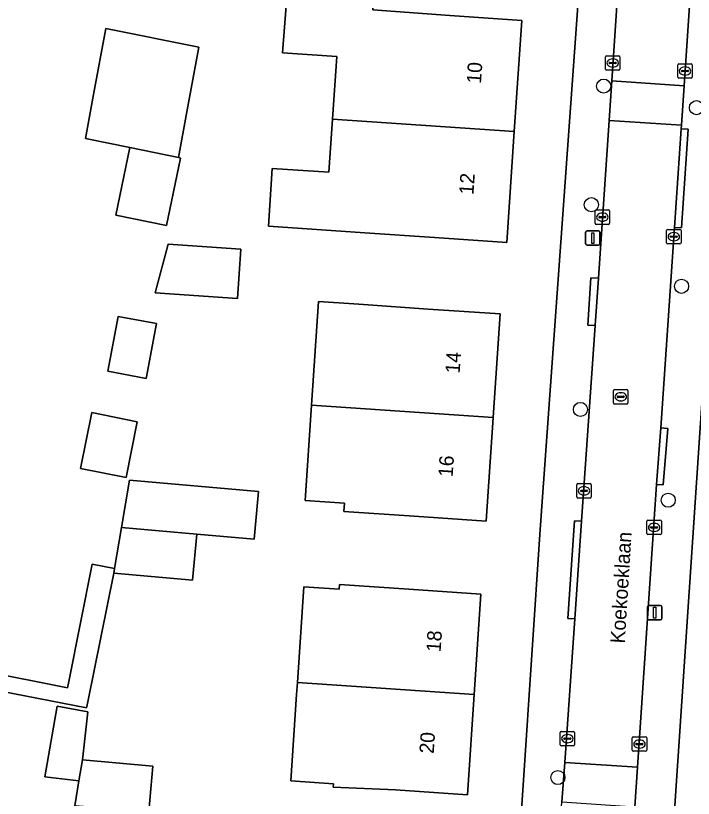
# Model space of a CAD drawing. Extents: x 161772 to 163126, y 383092 to 383917.
# Drawn here: x 162280.9 to 162327.9, y 383695.1 to 383749.3 of the extents above; entities that cross this region are included whole.
import ezdxf

# ---------------------------------------------------------------- set-up
doc = ezdxf.new("R2010")
doc.units = 0
for name, color, linetype in [('IMGEO_Boom', 7, 'Continuous'), ('IMGEO_Erf', 7, 'Continuous'), ('IMGEO_Kolk', 7, 'Continuous'), ('IMGEO_Lichtmast', 7, 'Continuous'), ('IMGEO_Openbare_ruimte_label', 7, 'Continuous'), ('IMGEO_Pand', 7, 'Continuous'), ('IMGEO_Pand_nummerreeks', 7, 'Continuous'), ('IMGEO_Rijbaan_lokaal_open', 7, 'Continuous'), ('IMGEO_Rioolput', 7, 'Continuous'), ('IMGEO_Voetpad_open', 7, 'Continuous')]:
    doc.layers.add(name, color=color, linetype=linetype)

msp = doc.modelspace()

# ---------------------------------------------------------------- linework, layer by layer
at = {"layer": 'IMGEO_Boom'}
for centre in [(162321.644, 383744.434), (162328.073, 383742.944), (162320.793, 383736.224), (162327.037, 383730.571), (162320.033, 383722.041), (162326.116, 383715.758), (162318.474, 383696.551)]:
    msp.add_circle(centre, 0.489, dxfattribs=at)
at = {"layer": 'IMGEO_Erf'}
for points in [[(162299.403, 383746.742), (162299.661, 383750), (162299.672, 383750.137), (162300.148, 383750.103), (162300.308, 383752.363), (162305.822, 383751.973), (162305.662, 383749.713), (162310.984, 383749.336), (162315.971, 383748.985), (162315.45, 383741.3), (162314.929, 383733.617), (162309.941, 383733.955), (162305.103, 383734.283), (162298.425, 383734.735), (162298.696, 383738.734), (162302.623, 383738.468), (162302.872, 383742.151), (162303.166, 383746.487)], [(162285.756, 383740.815), (162286.321, 383743.851), (162287.171, 383748.42), (162293.617, 383747.135), (162292.783, 383742.649), (162292.195, 383739.486), (162292.33, 383739.458), (162291.363, 383734.774), (162287.868, 383735.496), (162288.836, 383740.18)], [(162290.575, 383730.125), (162291.495, 383733.496), (162296.514, 383733.156), (162296.283, 383729.739)], [(162301.905, 383729.514), (162304.69, 383729.325), (162309.487, 383729), (162314.475, 383728.662), (162313.989, 383721.488), (162313.503, 383714.317), (162308.515, 383714.655), (162303.661, 383714.984), (162303.699, 383715.545), (162300.971, 383715.729), (162301.419, 383722.343)], [(162287.302, 383724.693), (162288.016, 383728.491), (162290.685, 383727.989), (162289.971, 383724.192)], [(162286.195, 383721.823), (162289.349, 383721.19), (162288.575, 383717.33), (162285.421, 383717.963)], [(162300.384, 383702.301), (162300.44, 383703.136), (162300.889, 383709.766), (162303.331, 383709.601), (162303.352, 383709.916), (162308.161, 383709.591), (162313.149, 383709.253), (162312.679, 383702.308), (162312.208, 383695.359), (162307.22, 383695.697), (162302.923, 383695.892), (162302.938, 383696.111), (162299.978, 383696.311)], [(162283.807, 383701.505), (162285.929, 383701.094), (162285.552, 383697.785), (162290.417, 383697.342), (162290.147, 383694.191), (162285.017, 383694.602), (162285.306, 383696.324), (162282.944, 383696.598)]]:
    msp.add_lwpolyline(points, close=True, dxfattribs=at)
for points in [[(162313.196, 383652.957), (162317.249, 383713.725), (162319.862, 383750)], [(162329.513, 383738.311), (162323.298, 383645.721), (162324.273, 383644.745), (162401.886, 383657.92)], [(162278.578, 383703.948), (162284.515, 383702.757), (162284.601, 383703.204), (162286.234, 383711.335), (162287.776, 383711.032), (162288.253, 383713.871), (162288.804, 383717.152), (162297.73, 383716.357), (162297.436, 383713.053), (162293.462, 383713.407), (162293.178, 383710.225), (162287.722, 383710.711), (162285.922, 383701.797), (162285.84, 383701.374), (162277.263, 383703.035)]]:
    msp.add_lwpolyline(points, dxfattribs=at)
at = {"layer": 'IMGEO_Kolk'}
for p, q in [((162321.77, 383745.614), (162321.77, 383746.466)), ((162321.845, 383746.54), (162322.697, 383746.54)), ((162322.029, 383746.034), (162322.029, 383746.046)), ((162322.072, 383746.083), (162322.47, 383746.083)), ((162322.258, 383746.32), (162322.283, 383746.32)), ((162322.513, 383746.046), (162322.513, 383746.034)), ((162322.771, 383746.466), (162322.771, 383745.614)), ((162322.697, 383745.54), (162321.845, 383745.54)), ((162322.467, 383745.997), (162322.069, 383745.997)), ((162322.281, 383745.76), (162322.256, 383745.76)), ((162326.779, 383745.056), (162326.779, 383745.908)), ((162326.854, 383745.982), (162327.706, 383745.982)), ((162327.038, 383745.476), (162327.038, 383745.488)), ((162327.081, 383745.525), (162327.479, 383745.525)), ((162327.267, 383745.762), (162327.292, 383745.762)), ((162327.522, 383745.488), (162327.522, 383745.476)), ((162327.78, 383745.908), (162327.78, 383745.056)), ((162327.706, 383744.982), (162326.854, 383744.982)), ((162327.476, 383745.439), (162327.078, 383745.439)), ((162327.29, 383745.202), (162327.265, 383745.202)), ((162321.054, 383734.938), (162321.054, 383735.79)), ((162321.129, 383735.864), (162321.981, 383735.864)), ((162322.055, 383735.79), (162322.055, 383734.938)), ((162321.313, 383735.358), (162321.313, 383735.37)), ((162321.751, 383735.321), (162321.353, 383735.321)), ((162321.356, 383735.407), (162321.754, 383735.407)), ((162321.542, 383735.644), (162321.567, 383735.644)), ((162321.797, 383735.37), (162321.797, 383735.358)), ((162321.981, 383734.864), (162321.129, 383734.864)), ((162321.565, 383735.084), (162321.54, 383735.084)), ((162326.002, 383733.582), (162326.002, 383734.434)), ((162326.077, 383734.508), (162326.929, 383734.508)), ((162326.49, 383734.288), (162326.515, 383734.288)), ((162327.003, 383734.434), (162327.003, 383733.582)), ((162326.261, 383734.002), (162326.261, 383734.014)), ((162326.699, 383733.965), (162326.301, 383733.965)), ((162326.304, 383734.051), (162326.702, 383734.051)), ((162326.513, 383733.728), (162326.488, 383733.728)), ((162326.745, 383734.014), (162326.745, 383734.002)), ((162326.929, 383733.508), (162326.077, 383733.508)), ((162319.782, 383715.981), (162319.782, 383716.833)), ((162319.857, 383716.907), (162320.709, 383716.907)), ((162320.783, 383716.833), (162320.783, 383715.981)), ((162320.041, 383716.401), (162320.041, 383716.413)), ((162320.479, 383716.364), (162320.081, 383716.364)), ((162320.084, 383716.45), (162320.482, 383716.45)), ((162320.27, 383716.687), (162320.295, 383716.687)), ((162320.525, 383716.413), (162320.525, 383716.401)), ((162320.709, 383715.907), (162319.857, 383715.907)), ((162320.293, 383716.127), (162320.268, 383716.127)), ((162324.639, 383713.448), (162324.639, 383714.3)), ((162324.714, 383714.374), (162325.566, 383714.374)), ((162325.127, 383714.154), (162325.152, 383714.154)), ((162325.64, 383714.3), (162325.64, 383713.448)), ((162324.898, 383713.868), (162324.898, 383713.88)), ((162325.336, 383713.831), (162324.938, 383713.831)), ((162324.941, 383713.917), (162325.339, 383713.917)), ((162325.15, 383713.594), (162325.125, 383713.594)), ((162325.382, 383713.88), (162325.382, 383713.868)), ((162325.566, 383713.374), (162324.714, 383713.374)), ((162318.631, 383698.819), (162318.631, 383699.671)), ((162318.706, 383699.745), (162319.558, 383699.745)), ((162319.119, 383699.525), (162319.144, 383699.525)), ((162319.632, 383699.671), (162319.632, 383698.819)), ((162318.89, 383699.239), (162318.89, 383699.251)), ((162319.328, 383699.202), (162318.93, 383699.202)), ((162318.933, 383699.288), (162319.331, 383699.288)), ((162319.142, 383698.965), (162319.117, 383698.965)), ((162319.374, 383699.251), (162319.374, 383699.239)), ((162323.623, 383698.442), (162323.623, 383699.294)), ((162323.698, 383699.368), (162324.55, 383699.368)), ((162323.882, 383698.862), (162323.882, 383698.874)), ((162323.925, 383698.911), (162324.323, 383698.911)), ((162324.111, 383699.148), (162324.136, 383699.148)), ((162324.366, 383698.874), (162324.366, 383698.862)), ((162324.624, 383699.294), (162324.624, 383698.442)), ((162319.558, 383698.745), (162318.706, 383698.745)), ((162324.55, 383698.368), (162323.698, 383698.368)), ((162324.32, 383698.825), (162323.922, 383698.825)), ((162324.134, 383698.588), (162324.109, 383698.588))]:
    msp.add_line(p, q, dxfattribs=at)
for points in [[(162321.77, 383745.614), (162321.77, 383746.466)], [(162321.845, 383746.54), (162322.697, 383746.54)], [(162322.771, 383746.466), (162322.771, 383745.614)], [(162322.697, 383745.54), (162321.845, 383745.54)], [(162326.779, 383745.056), (162326.779, 383745.908)], [(162326.854, 383745.982), (162327.706, 383745.982)], [(162327.78, 383745.908), (162327.78, 383745.056)], [(162327.706, 383744.982), (162326.854, 383744.982)], [(162321.054, 383734.938), (162321.054, 383735.79)], [(162321.129, 383735.864), (162321.981, 383735.864)], [(162322.055, 383735.79), (162322.055, 383734.938)], [(162321.981, 383734.864), (162321.129, 383734.864)], [(162326.002, 383733.582), (162326.002, 383734.434)], [(162326.077, 383734.508), (162326.929, 383734.508)], [(162327.003, 383734.434), (162327.003, 383733.582)], [(162326.929, 383733.508), (162326.077, 383733.508)], [(162319.782, 383715.981), (162319.782, 383716.833)], [(162319.857, 383716.907), (162320.709, 383716.907)], [(162320.783, 383716.833), (162320.783, 383715.981)], [(162320.709, 383715.907), (162319.857, 383715.907)], [(162324.639, 383713.448), (162324.639, 383714.3)], [(162324.714, 383714.374), (162325.566, 383714.374)], [(162325.64, 383714.3), (162325.64, 383713.448)], [(162325.566, 383713.374), (162324.714, 383713.374)], [(162318.631, 383698.819), (162318.631, 383699.671)], [(162318.706, 383699.745), (162319.558, 383699.745)], [(162319.632, 383699.671), (162319.632, 383698.819)], [(162323.623, 383698.442), (162323.623, 383699.294)], [(162323.698, 383699.368), (162324.55, 383699.368)], [(162324.624, 383699.294), (162324.624, 383698.442)], [(162319.558, 383698.745), (162318.706, 383698.745)], [(162324.55, 383698.368), (162323.698, 383698.368)]]:
    msp.add_lwpolyline(points, dxfattribs=at)
for centre, radius, start, end in [((162321.847, 383746.464), 0.0765, 91.552, 178.448), ((162321.847, 383746.464), 0.0765, 91.552, 178.448), ((162322.069, 383746.043), 0.0403, 85.8775, 175.7526), ((162322.066, 383746.033), 0.0366, 178.938, 274.7102), ((162322.47, 383746.04), 0.043, 264.8664, 352.4533), ((162322.474, 383746.045), 0.0386, 1.7309, 96.639), ((162322.695, 383746.464), 0.0765, 1.552, 88.448), ((162322.695, 383746.464), 0.0765, 1.552, 88.448), ((162321.847, 383745.616), 0.0765, 181.552, 268.448), ((162321.847, 383745.616), 0.0765, 181.552, 268.448), ((162322.695, 383745.616), 0.0765, 271.552, 358.448), ((162322.695, 383745.616), 0.0765, 271.552, 358.448), ((162326.856, 383745.906), 0.0765, 91.552, 178.448), ((162326.856, 383745.906), 0.0765, 91.552, 178.448), ((162327.078, 383745.485), 0.0403, 85.8775, 175.7526), ((162327.075, 383745.475), 0.0366, 178.938, 274.7102), ((162327.479, 383745.482), 0.043, 264.8664, 352.4533), ((162327.483, 383745.487), 0.0386, 1.7309, 96.639), ((162327.704, 383745.906), 0.0765, 1.552, 88.448), ((162327.704, 383745.906), 0.0765, 1.552, 88.448), ((162326.856, 383745.058), 0.0765, 181.552, 268.448), ((162326.856, 383745.058), 0.0765, 181.552, 268.448), ((162327.704, 383745.058), 0.0765, 271.552, 358.448), ((162327.704, 383745.058), 0.0765, 271.552, 358.448), ((162321.131, 383735.788), 0.0765, 91.552, 178.448), ((162321.131, 383735.788), 0.0765, 91.552, 178.448), ((162321.979, 383735.788), 0.0765, 1.552, 88.448), ((162321.979, 383735.788), 0.0765, 1.552, 88.448), ((162321.353, 383735.367), 0.0403, 85.8775, 175.7526), ((162321.35, 383735.357), 0.0366, 178.938, 274.7102), ((162321.754, 383735.364), 0.043, 264.8664, 352.4533), ((162321.758, 383735.369), 0.0386, 1.7309, 96.639), ((162321.131, 383734.94), 0.0765, 181.552, 268.448), ((162321.131, 383734.94), 0.0765, 181.552, 268.448), ((162321.979, 383734.94), 0.0765, 271.552, 358.448), ((162321.979, 383734.94), 0.0765, 271.552, 358.448), ((162326.079, 383734.432), 0.0765, 91.552, 178.448), ((162326.079, 383734.432), 0.0765, 91.552, 178.448), ((162326.927, 383734.432), 0.0765, 1.552, 88.448), ((162326.927, 383734.432), 0.0765, 1.552, 88.448), ((162326.079, 383733.584), 0.0765, 181.552, 268.448), ((162326.079, 383733.584), 0.0765, 181.552, 268.448), ((162326.301, 383734.011), 0.0403, 85.8775, 175.7526), ((162326.298, 383734.001), 0.0366, 178.938, 274.7102), ((162326.702, 383734.008), 0.043, 264.8664, 352.4533), ((162326.706, 383734.013), 0.0386, 1.7309, 96.639), ((162326.927, 383733.584), 0.0765, 271.552, 358.448), ((162326.927, 383733.584), 0.0765, 271.552, 358.448), ((162319.859, 383716.831), 0.0765, 91.552, 178.448), ((162319.859, 383716.831), 0.0765, 91.552, 178.448), ((162320.707, 383716.831), 0.0765, 1.552, 88.448), ((162320.707, 383716.831), 0.0765, 1.552, 88.448), ((162320.081, 383716.41), 0.0403, 85.8775, 175.7526), ((162320.078, 383716.4), 0.0366, 178.938, 274.7102), ((162320.482, 383716.407), 0.043, 264.8664, 352.4533), ((162320.486, 383716.412), 0.0386, 1.7309, 96.639), ((162319.859, 383715.983), 0.0765, 181.552, 268.448), ((162319.859, 383715.983), 0.0765, 181.552, 268.448), ((162320.707, 383715.983), 0.0765, 271.552, 358.448), ((162320.707, 383715.983), 0.0765, 271.552, 358.448), ((162324.716, 383714.298), 0.0765, 91.552, 178.448), ((162324.716, 383714.298), 0.0765, 91.552, 178.448), ((162325.564, 383714.298), 0.0765, 1.552, 88.448), ((162325.564, 383714.298), 0.0765, 1.552, 88.448), ((162324.938, 383713.877), 0.0403, 85.8775, 175.7526), ((162324.935, 383713.867), 0.0366, 178.938, 274.7102), ((162325.339, 383713.874), 0.043, 264.8664, 352.4533), ((162325.343, 383713.879), 0.0386, 1.7309, 96.639), ((162324.716, 383713.45), 0.0765, 181.552, 268.448), ((162324.716, 383713.45), 0.0765, 181.552, 268.448), ((162325.564, 383713.45), 0.0765, 271.552, 358.448), ((162325.564, 383713.45), 0.0765, 271.552, 358.448), ((162318.708, 383699.669), 0.0765, 91.552, 178.448), ((162318.708, 383699.669), 0.0765, 91.552, 178.448), ((162319.556, 383699.669), 0.0765, 1.552, 88.448), ((162319.556, 383699.669), 0.0765, 1.552, 88.448), ((162318.93, 383699.248), 0.0403, 85.8775, 175.7526), ((162318.927, 383699.238), 0.0366, 178.938, 274.7102), ((162319.331, 383699.245), 0.043, 264.8664, 352.4533), ((162319.335, 383699.25), 0.0386, 1.7309, 96.639), ((162323.7, 383699.292), 0.0765, 91.552, 178.448), ((162323.7, 383699.292), 0.0765, 91.552, 178.448), ((162323.922, 383698.871), 0.0403, 85.8775, 175.7526), ((162323.919, 383698.861), 0.0366, 178.938, 274.7102), ((162324.323, 383698.868), 0.043, 264.8664, 352.4533), ((162324.327, 383698.873), 0.0386, 1.7309, 96.639), ((162324.548, 383699.292), 0.0765, 1.552, 88.448), ((162324.548, 383699.292), 0.0765, 1.552, 88.448), ((162318.708, 383698.821), 0.0765, 181.552, 268.448), ((162318.708, 383698.821), 0.0765, 181.552, 268.448), ((162319.556, 383698.821), 0.0765, 271.552, 358.448), ((162319.556, 383698.821), 0.0765, 271.552, 358.448), ((162323.7, 383698.444), 0.0765, 181.552, 268.448), ((162323.7, 383698.444), 0.0765, 181.552, 268.448), ((162324.548, 383698.444), 0.0765, 271.552, 358.448), ((162324.548, 383698.444), 0.0765, 271.552, 358.448)]:
    msp.add_arc(centre, radius, start, end, dxfattribs=at)
for centre, major_axis, ratio, start_param, end_param in [((162322.257, 383746.04), (-0.387, 0.002), 0.722429, 4.712389, 7.853982), ((162322.282, 383746.04), (-0.39, 0.002), 0.717154, 1.570796, 4.712389), ((162327.266, 383745.482), (-0.387, 0.002), 0.722429, 4.712389, 7.853982), ((162327.291, 383745.482), (-0.39, 0.002), 0.717154, 1.570796, 4.712389), ((162321.541, 383735.364), (-0.387, 0.002), 0.722429, 4.712389, 7.853982), ((162321.566, 383735.364), (-0.39, 0.002), 0.717154, 1.570796, 4.712389), ((162326.489, 383734.008), (-0.387, 0.002), 0.722429, 4.712389, 7.853982), ((162326.514, 383734.008), (-0.39, 0.002), 0.717154, 1.570796, 4.712389), ((162320.269, 383716.407), (-0.387, 0.002), 0.722429, 4.712389, 7.853982), ((162320.294, 383716.407), (-0.39, 0.002), 0.717154, 1.570796, 4.712389), ((162325.126, 383713.874), (-0.387, 0.002), 0.722429, 4.712389, 7.853982), ((162325.151, 383713.874), (-0.39, 0.002), 0.717154, 1.570796, 4.712389), ((162319.118, 383699.245), (-0.387, 0.002), 0.722429, 4.712389, 7.853982), ((162319.143, 383699.245), (-0.39, 0.002), 0.717154, 1.570796, 4.712389), ((162324.11, 383698.868), (-0.387, 0.002), 0.722429, 4.712389, 7.853982), ((162324.135, 383698.868), (-0.39, 0.002), 0.717154, 1.570796, 4.712389)]:
    msp.add_ellipse(centre, major_axis=major_axis, ratio=ratio, start_param=start_param, end_param=end_param, dxfattribs=at)
at = {"layer": 'IMGEO_Lichtmast'}
for p, q in [((162320.397, 383733.512), (162320.397, 383734.312)), ((162320.397, 383734.312), (162320.397, 383733.512)), ((162320.497, 383734.412), (162321.287, 383734.412)), ((162321.287, 383734.412), (162320.497, 383734.412)), ((162321.387, 383734.312), (162321.387, 383733.512)), ((162321.387, 383733.512), (162321.387, 383734.312)), ((162321.287, 383733.412), (162320.497, 383733.412)), ((162320.497, 383733.412), (162321.287, 383733.412)), ((162324.679, 383707.567), (162324.679, 383708.367)), ((162324.679, 383708.367), (162324.679, 383707.567)), ((162324.779, 383708.467), (162325.569, 383708.467)), ((162325.569, 383708.467), (162324.779, 383708.467)), ((162325.669, 383708.367), (162325.669, 383707.567)), ((162325.669, 383707.567), (162325.669, 383708.367)), ((162325.569, 383707.467), (162324.779, 383707.467)), ((162324.779, 383707.467), (162325.569, 383707.467))]:
    msp.add_line(p, q, dxfattribs=at)
for points in [[(162320.817, 383734.287), (162320.967, 383734.287), (162320.967, 383733.537), (162320.817, 383733.537), (162320.817, 383734.287)], [(162325.099, 383708.342), (162325.249, 383708.342), (162325.249, 383707.592), (162325.099, 383707.592), (162325.099, 383708.342)]]:
    msp.add_lwpolyline(points, dxfattribs=at)
for centre, start, end in [((162320.497, 383734.312), 90, 180), ((162320.497, 383734.312), 90, 180), ((162321.287, 383734.312), 0, 90), ((162321.287, 383734.312), 360, 90), ((162320.497, 383733.512), 180, 270), ((162320.497, 383733.512), 180, 270), ((162321.287, 383733.512), 270, 0), ((162321.287, 383733.512), 270, 0), ((162324.779, 383708.367), 90, 180), ((162324.779, 383708.367), 90, 180), ((162325.569, 383708.367), 0, 90), ((162325.569, 383708.367), 360, 90), ((162324.779, 383707.567), 180, 270), ((162324.779, 383707.567), 180, 270), ((162325.569, 383707.567), 270, 0), ((162325.569, 383707.567), 270, 0)]:
    msp.add_arc(centre, 0.1, start, end, dxfattribs=at)
at = {"layer": 'IMGEO_Pand'}
for points in [[(162315.971, 383748.985), (162310.984, 383749.336), (162305.662, 383749.713), (162305.822, 383751.973), (162300.308, 383752.363), (162300.148, 383750.103), (162299.672, 383750.137), (162299.661, 383750), (162299.403, 383746.742), (162303.166, 383746.487), (162302.872, 383742.151), (162315.45, 383741.3)], [(162288.836, 383740.18), (162292.195, 383739.486), (162292.783, 383742.649), (162293.617, 383747.135), (162287.171, 383748.42), (162286.321, 383743.851), (162285.756, 383740.815)], [(162315.45, 383741.3), (162302.872, 383742.151), (162302.623, 383738.468), (162298.696, 383738.734), (162298.425, 383734.735), (162305.103, 383734.283), (162309.941, 383733.955), (162314.929, 383733.617)], [(162288.836, 383740.18), (162287.868, 383735.496), (162291.363, 383734.774), (162292.33, 383739.458), (162292.195, 383739.486)], [(162291.495, 383733.496), (162290.575, 383730.125), (162296.283, 383729.739), (162296.514, 383733.156)], [(162301.419, 383722.343), (162313.989, 383721.488), (162314.475, 383728.662), (162309.487, 383729), (162304.69, 383729.325), (162301.905, 383729.514)], [(162289.971, 383724.192), (162290.685, 383727.989), (162288.016, 383728.491), (162287.302, 383724.693)], [(162301.419, 383722.343), (162300.971, 383715.729), (162303.699, 383715.545), (162303.661, 383714.984), (162308.515, 383714.655), (162313.503, 383714.317), (162313.989, 383721.488)], [(162288.575, 383717.33), (162289.349, 383721.19), (162286.195, 383721.823), (162285.421, 383717.963)], [(162297.73, 383716.357), (162288.804, 383717.152), (162288.253, 383713.871), (162293.462, 383713.407), (162297.436, 383713.053)], [(162293.462, 383713.407), (162288.253, 383713.871), (162287.776, 383711.032), (162287.722, 383710.711), (162293.178, 383710.225)], [(162300.44, 383703.136), (162312.679, 383702.308), (162313.149, 383709.253), (162308.161, 383709.591), (162303.352, 383709.916), (162303.331, 383709.601), (162300.889, 383709.766)], [(162300.44, 383703.136), (162300.384, 383702.301), (162299.978, 383696.311), (162302.938, 383696.111), (162302.923, 383695.892), (162307.22, 383695.697), (162312.208, 383695.359), (162312.679, 383702.308)], [(162283.807, 383701.505), (162282.944, 383696.598), (162285.306, 383696.324), (162285.552, 383697.785), (162285.929, 383701.094)], [(162285.552, 383697.785), (162285.306, 383696.324), (162285.017, 383694.602), (162290.147, 383694.191), (162290.417, 383697.342)]]:
    msp.add_lwpolyline(points, close=True, dxfattribs=at)
at = {"layer": 'IMGEO_Rijbaan_lokaal_open'}
for points in [[(162327.904, 383754.6), (162328.166, 383758.408), (162330.319, 383789.642), (162325.316, 383789.988), (162322.549, 383750), (162322.2, 383744.798), (162327.215, 383744.461), (162327.587, 383750)], [(162322.016, 383742.063), (162327.031, 383741.726), (162327.215, 383744.461), (162322.2, 383744.798)], [(162325.594, 383720.759), (162326.555, 383734.645), (162327.015, 383741.486), (162327.031, 383741.726), (162322.016, 383742.063), (162321.282, 383731.126), (162321.062, 383727.852), (162320.113, 383714.297), (162319.639, 383707.534), (162318.944, 383697.598), (162323.98, 383697.26), (162325.296, 383716.851)], [(162323.98, 383697.26), (162318.944, 383697.598), (162318.752, 383694.86), (162323.796, 383694.521)]]:
    msp.add_lwpolyline(points, close=True, dxfattribs=at)
at = {"layer": 'IMGEO_Rioolput'}
for p, q in [((162322.327, 383722.494), (162322.327, 383723.346)), ((162322.402, 383723.42), (162323.254, 383723.42)), ((162323.328, 383723.346), (162323.328, 383722.494)), ((162322.586, 383722.914), (162322.586, 383722.926)), ((162323.024, 383722.877), (162322.626, 383722.877)), ((162322.629, 383722.963), (162323.027, 383722.963)), ((162322.815, 383723.2), (162322.84, 383723.2)), ((162323.07, 383722.926), (162323.07, 383722.914)), ((162323.254, 383722.42), (162322.402, 383722.42)), ((162322.838, 383722.64), (162322.813, 383722.64))]:
    msp.add_line(p, q, dxfattribs=at)
for points in [[(162322.327, 383722.494), (162322.327, 383723.346)], [(162322.402, 383723.42), (162323.254, 383723.42)], [(162323.328, 383723.346), (162323.328, 383722.494)], [(162323.254, 383722.42), (162322.402, 383722.42)]]:
    msp.add_lwpolyline(points, dxfattribs=at)
for centre, radius, start, end in [((162322.404, 383723.344), 0.0765, 91.552, 178.448), ((162322.404, 383723.344), 0.0765, 91.552, 178.448), ((162323.252, 383723.344), 0.0765, 1.552, 88.448), ((162323.252, 383723.344), 0.0765, 1.552, 88.448), ((162322.626, 383722.923), 0.0403, 85.8775, 175.7526), ((162322.623, 383722.913), 0.0366, 178.938, 274.7102), ((162323.027, 383722.92), 0.043, 264.8664, 352.4533), ((162323.031, 383722.925), 0.0386, 1.7309, 96.639), ((162322.404, 383722.496), 0.0765, 181.552, 268.448), ((162322.404, 383722.496), 0.0765, 181.552, 268.448), ((162323.252, 383722.496), 0.0765, 271.552, 358.448), ((162323.252, 383722.496), 0.0765, 271.552, 358.448)]:
    msp.add_arc(centre, radius, start, end, dxfattribs=at)
for centre, major_axis, ratio, start_param, end_param in [((162322.814, 383722.92), (-0.387, 0.002), 0.722429, 4.712389, 7.853982), ((162322.839, 383722.92), (-0.39, 0.002), 0.717154, 1.570796, 4.712389)]:
    msp.add_ellipse(centre, major_axis=major_axis, ratio=ratio, start_param=start_param, end_param=end_param, dxfattribs=at)
at = {"layer": 'IMGEO_Voetpad_open'}
for points in [[(162325.595, 383801.714), (162321.904, 383800.852), (162322.139, 383797.223), (162321.727, 383778.3), (162319.862, 383750), (162317.249, 383713.725), (162313.196, 383652.957), (162312.79, 383644.774), (162310.606, 383642.128), (162314.799, 383642.8)], [(162321.062, 383727.852), (162320.547, 383727.883), (162320.758, 383731.158), (162321.282, 383731.126), (162322.016, 383742.063), (162322.2, 383744.798), (162322.549, 383750), (162325.316, 383789.988), (162325.61, 383794.248), (162326.088, 383800.147)], [(162327.904, 383754.6), (162327.587, 383750), (162327.215, 383744.461), (162327.031, 383741.726), (162327.015, 383741.486), (162327.499, 383741.457), (162327.044, 383734.616), (162326.555, 383734.645), (162325.594, 383720.759), (162326.081, 383720.722), (162325.767, 383716.815), (162325.296, 383716.851), (162323.98, 383697.26), (162323.796, 383694.521), (162323.406, 383688.717), (162323.962, 383688.68), (162323.277, 383678.842), (162322.744, 383678.877), (162321.3, 383657.411), (162321.109, 383654.576), (162320.508, 383648.472)], [(162318.421, 383643.648), (162324.273, 383644.745), (162323.298, 383645.721), (162329.513, 383738.311)], [(162315.287, 383645.208), (162315.966, 383654.921), (162316.164, 383657.756), (162318.027, 383684.506), (162318.752, 383694.86), (162318.944, 383697.598), (162319.639, 383707.534), (162319.171, 383707.562), (162319.616, 383714.327), (162320.113, 383714.297), (162321.062, 383727.852)]]:
    msp.add_lwpolyline(points, dxfattribs=at)
for points in [[(162326.555, 383734.645), (162327.044, 383734.616), (162327.499, 383741.457), (162327.015, 383741.486)], [(162321.062, 383727.852), (162321.282, 383731.126), (162320.758, 383731.158), (162320.547, 383727.883)], [(162325.594, 383720.759), (162325.296, 383716.851), (162325.767, 383716.815), (162326.081, 383720.722)], [(162320.113, 383714.297), (162319.616, 383714.327), (162319.171, 383707.562), (162319.639, 383707.534)], [(162287.722, 383710.711), (162287.776, 383711.032), (162286.234, 383711.335), (162284.601, 383703.204), (162284.515, 383702.757), (162278.578, 383703.948), (162278.53, 383703.711), (162272.677, 383704.886), (162255.783, 383708.274), (162255.603, 383707.378), (162277.263, 383703.035), (162285.84, 383701.374), (162285.922, 383701.797)]]:
    msp.add_lwpolyline(points, close=True, dxfattribs=at)

# ---------------------------------------------------------------- texts
at = {"layer": 'IMGEO_Openbare_ruimte_label'}
msp.add_text('Koekoeklaan', height=1, rotation=86.4451, dxfattribs=at).set_placement((162323.104, 383705.817))
at = {"layer": 'IMGEO_Pand_nummerreeks'}
for s, rotation, p in [('10', 86.1213, (162313.146, 383744.583)), ('12', 86.1211, (162312.625, 383736.893)), ('14', 86.1236, (162311.669, 383724.513)), ('16', 86.1236, (162311.183, 383717.34)), ('18', 86.1254, (162310.35, 383705.219)), ('20', 86.1254, (162309.874, 383698.181))]:
    msp.add_text(s, height=1, rotation=rotation, dxfattribs=at).set_placement(p)

doc.saveas('drawing.dxf')
